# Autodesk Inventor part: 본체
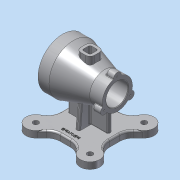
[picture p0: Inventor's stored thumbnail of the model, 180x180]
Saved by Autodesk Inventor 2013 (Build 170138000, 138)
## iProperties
Created: 2018-03
Part Number: 본체
Material: 알루미늄 6061
Document SubType Name: Modeling
Designer: dgall
Density: 2.71 g/cm^3
Mass: 1013.63 g
Surface Area: 870.735 cm^2
Volume: 374.034 cm^3
Author: dgall
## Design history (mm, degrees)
sketch "스케치1"
  geometry: L1 (0, 0)-(-68.205, 68.205); L2 (0, 0)-(-76.473, 0); L3 (-35.239, 60.483)-(-27.078, 52.322); L4 (-60.483, 35.239)-(-52.322, 27.078); L5 (-35.239, -60.483)-(-27.078, -52.322); L6 (-60.483, -35.239)-(-52.322, -27.078); L7 (0, 0)-(0, -76.473); L8 (0, 0)-(-68.205, -68.205); L9 (60.483, -35.239)-(52.322, -27.078); L10 (35.239, -60.483)-(27.078, -52.322); L11 (0, 0)-(76.473, 0); L12 (0, 0)-(68.205, -68.205); L13 (35.239, 60.483)-(27.078, 52.322); L14 (60.483, 35.239)-(52.322, 27.078); L15 (0, 0)-(0, 76.473); L16 (0, 0)-(68.205, 68.205); L17 (-9.4, 45)-(9.4, 45); L18 (32.068, 45)-(45, 45); L19 (45, 45)-(45, 32.068); L20 (45, 9.4)-(45, -9.4); L21 (45, -32.068)-(45, -45); L22 (45, -45)-(32.068, -45); L23 (9.4, -45)-(-9.4, -45); L24 (-32.068, -45)-(-45, -45); L25 (-45, -45)-(-45, -32.068); L26 (-45, -9.4)-(-45, 9.4); C1 r 5 at (-49.497, 49.497); C2 r 5 at (-49.497, -49.497); C3 r 5 at (49.497, -49.497); C4 r 5 at (49.497, 49.497); A1 r 18 centre (-49.497, 49.497) between (-35.239, 60.483) and (-60.483, 35.239); A2 r 25 centre (-9.4, 70) between (-27.078, 52.322) and (-9.4, 45); A3 r 25 centre (-70, 9.4) between (-45, 9.4) and (-52.322, 27.078); A4 r 18 centre (-49.497, -49.497) between (-60.483, -35.239) and (-35.239, -60.483); A5 r 25 centre (-70, -9.4) between (-52.322, -27.078) and (-45, -9.4); A6 r 25 centre (-9.4, -70) between (-9.4, -45) and (-27.078, -52.322); A7 r 18 centre (49.497, -49.497) between (35.239, -60.483) and (60.483, -35.239); A8 r 25 centre (9.4, -70) between (27.078, -52.322) and (9.4, -45); A9 r 25 centre (70, -9.4) between (45, -9.4) and (52.322, -27.078); A10 r 18 centre (49.497, 49.497) between (60.483, 35.239) and (35.239, 60.483); A11 r 25 centre (70, 9.4) between (52.322, 27.078) and (45, 9.4); A12 r 25 centre (9.4, 70) between (9.4, 45) and (27.078, 52.322); 5 further points
  constraints: 52 end point, 30 point on circle, 16 centre point, 13 parallel, 6 perpendicular, 6 tangent, 5 coincident, 4 horizontal, 4 point on line, 1 equal radius, 89 other
  dimensions: "d1" = 45 deg angle of L2 L1; "d2" = 10 diameter of C1; "d3" = 36 diameter of A1; "d4" = 90 distance of point (-45, 45) L18.end; "d5" = 90 distance of L18.end L21.end; "d6" = 25 radius of A2; "d9" = 360 deg dimension on point (0, 0) point (-45, 45) (derived)
extrude "돌출1" new body sketch "스케치1" distance "d11" = 12; taper "d12" = 0 deg
sketch "스케치2"
  geometry: L1 (-50, 82)-(50, 82); L2 (9.4, 0)-(27.078, 0) reference; L3 (0, 0)-(0, 110.069); L4 (-50, 127)-(-30, 127); L5 (-30, 127)-(27, 109.5); L6 (27, 109.5)-(50, 109.5); L7 (50, 109.5)-(50, 82); L8 (-50, 127)-(-50, 82)
  constraints: 14 end point, 2 parallel, 2 perpendicular, 1 horizontal
  dimensions: "d13" = 82 distance between parallel lines of L1 L2; "d14" = 50 distance from line of L4.start L3; "d15" = 20 distance of L4.start L4.end; "d16" = 77 horizontal distance of L5.end L4.start; "d17" = 100 horizontal distance of L4.start L6.end; "d19" = 90 diameter of L4 L1; "d21" = 55 diameter of L6 L1
revolve "회전1" sketch "스케치2" stored, may be unused: angle "d22" = 90 deg
sketch "스케치3"
  geometry: L1 (50, 54.5)-(50, 109.5) reference; L2 (50, 82)-(-50, 82); L3 (-50, 37)-(-50, 127) reference; L4 (-50, 82)-(-27, 82); L5 (-27, 82)-(-27, 117); L6 (-27, 117)-(-50, 117); L7 (-50, 117)-(-50, 82); L8 (-27, 82)-(20, 82); L9 (20, 82)-(20, 108); L10 (20, 108)-(-27, 108); L11 (-27, 108)-(-27, 82); L12 (20, 82)-(50, 82); L13 (50, 82)-(50, 102); L14 (50, 102)-(20, 102); L15 (20, 102)-(20, 82); 1 further point
  constraints: 26 end point, 6 parallel, 3 horizontal, 3 perpendicular, 2 midpoint, 1 point on line
  dimensions: "d23" = 23 distance of L5.end L6.end; "d25" = 47 distance of L9.end L10.end; "d26" = 30 distance of L13.end L14.end (derived); "d27" = 70 diameter of L6 L2; "d28" = 52 diameter of L10 L8; "d29" = 40 diameter of L14 L2
revolve "회전2" sketch "스케치3" stored, may be unused: angle "d30" = 90 deg
sketch "스케치4"
  geometry: L1 (0, 0)-(52.632, 0); C1 r 27.5 at (0, 0) reference; A1 r 27.5 centre (0, 0) between (27.5, 0) and (26.609, -6.943); A2 r 7 centre (27.5, 0) between (26.609, -6.943) and (26.609, 6.943); 1 further point
  constraints: 5 point on circle, 2 centre point, 2 end point, 1 coincident, 1 horizontal, 1 point on line
  dimensions: "d31" = 55 diameter of A1; "d32" = 14 diameter of A2
extrude "돌출2" join sketch "스케치4" distance "d33" = 15; taper "d34" = 0 deg
sketch "스케치5"
  geometry: A1 r 7 centre (0, 0) between (-0.891, -6.943) and (-0.891, 6.943) reference; 1 further point
hole "구멍1" sketch "스케치5" at (0, 0) diameter "d38" = 2.459; stored, may be unused: countersink angle "d42" = 90 deg, drill point angle "d44" = 118 deg; dims "d39" = 9, "d40" = 4, "d41" = 2, "d43" = 11
fillet "모깎기1" dims "d48" = 3
fillet "모깎기2" dims "d49" = 1
fillet "모깎기3" dims "d50" = 3
fillet "모깎기4" dims "d51" = 1
fillet "모깎기5" dims "d52" = 3
fillet "모깎기6" dims "d53" = 1
sketch "스케치6"
  geometry: L1 (9.4, 12)-(27.078, 12) reference; L2 (9.4, 12)-(-9.4, 12) reference; L3 (0, 12)-(-24, 12); L4 (-27.078, 12)-(-9.4, 12) reference; L5 (0, 82)-(0, 54.5); L6 (0, 54.5)-(0, 12); L7 (-24, 12)-(-19.566, 62.676); C1 r 20 at (0, 82) reference; C2 r 26 at (0, 82) reference; C3 r 26 at (0, 82) reference; A1 r 27.5 centre (0, 82) between (-19.566, 62.676) and (0, 54.5) reference; A2 r 45 centre (0, 82) between (0, 37) and (-21.342, 42.383) reference; 2 further points
  constraints: 8 end point, 4 point on circle, 3 point on line, 2 perpendicular, 1 coincident, 1 midpoint
  dimensions: "d54" = 24 distance of L3.start L3.end
extrude "돌출3" join sketch "스케치6" stored distance "d58" = 8; taper "d59" = 0 deg
sketch "스케치7"
  geometry: L1 (0, 0)-(0, 140.05); L2 (0, 0)-(-37, 0); L3 (-27.078, 0)-(-9.4, 0) reference; L4 (35.239, 0)-(27.078, 0) reference; L5 (-50, 37)-(-30, 37) reference; L6 (-30, 37)-(27, 54.5) reference; L7 (-37, 0)-(-37, 37); L8 (-37, 37)-(-30, 37); L9 (-4, 44.982)-(-4, 12); L10 (-4, 51.223)-(-4, 12) reference; L11 (-4, 12)-(-37, 12); L12 (0, 12.216)-(37, 12.216); L13 (9.4, 0)-(27.078, 0) reference; L14 (27, 54.5)-(50, 54.5) reference; L15 (27, 54.5)-(50, 54.5) reference; L16 (37, 12.216)-(37, 54.5); L17 (27, 54.5)-(-4, 44.982)
  constraints: 18 end point, 5 point on line, 4 collinear, 3 perpendicular, 1 parallel, 1 vertical
  dimensions: "d60" = 37 distance of L1.start L2.end; "d63" = 37 distance of L12.start L12.end
extrude "돌출4" join sketch "스케치7" stored distance "d61" = 8; taper "d62" = 0 deg
sketch "스케치8" dims "d64" = 80
  geometry: L1 (0, 0)-(-50.939, 0); C1 r 45 at (0, 0) reference; 2 further points
  constraints: 2 end point, 1 coincident, 1 horizontal, 1 horizontal alignment, 1 point on line, 2 other
hole "구멍2" sketch "스케치8" at (-40, 0) diameter "d65" = 3.242; stored, may be unused: countersink angle "d69" = 90 deg, drill point angle "d71" = 118 deg; dims "d66" = 9, "d67" = 4, "d68" = 2, "d70" = 11
chamfer "모따기1" distance "d75" = 1; stored, may be unused: second distance "d76" = 2, angle "d77" = 45 deg
chamfer "모따기2" distance "d78" = 1; stored, may be unused: second distance "d79" = 2, angle "d80" = 45 deg
fillet "모깎기7" dims "d81" = 3
fillet "모깎기8" dims "d82" = 3
fillet "모깎기9" dims "d83" = 3
fillet "모깎기10" dims "d84" = 3
fillet "모깎기11" dims "d85" = 3
fillet "모깎기12" dims "d86" = 3
fillet "모깎기13" dims "d87" = 3
fillet "모깎기14" dims "d88" = 3
fillet "모깎기15" dims "d89" = 3
fillet "모깎기16" dims "d90" = 3
fillet "모깎기17" dims "d91" = 3
fillet "모깎기18" dims "d92" = 3
fillet "모깎기19" dims "d93" = 3
sketch "스케치9"
  geometry: L1 (-45, 9.4)-(-45, -9.4) reference; 2 further points
  constraints: 1 other
  dimensions: "d94" = 45 distance from line of L1 point (0, 35); "d95" = 35 distance of point (0, 35) point (0, 0)
feature "엠보싱1" sketch "스케치9" dims "d9" = 360 deg (derived), "d96" = 0.5, "d97" = 0
node "작업 평면1"
sketch "스케치10"
  geometry: L1 (12.5, -12.5)-(-12.5, -12.5); L2 (-12.5, -12.5)-(-12.5, 12.5); L3 (-12.5, 12.5)-(12.5, 12.5); L4 (12.5, 12.5)-(12.5, -12.5); L5 (12.5, -12.5)-(-12.5, 12.5); L6 (-12.5, -12.5)-(12.5, 12.5); L7 (7.5, -7.5)-(-7.5, -7.5); L8 (-7.5, -7.5)-(-7.5, 7.5); L9 (-7.5, 7.5)-(7.5, 7.5); L10 (7.5, 7.5)-(7.5, -7.5); L11 (7.5, -7.5)-(-7.5, 7.5); L12 (-7.5, -7.5)-(7.5, 7.5); 1 further point
  constraints: 24 end point, 4 midpoint, 4 parallel, 2 horizontal, 2 perpendicular, 1 point on line
  dimensions: "d99" = 25 distance of L2.end L3.end; "d101" = 15 distance of L8.end L9.end; "d102" = 25 distance of L1.end L2.end; "d103" = 15 distance of L7.end L8.end (derived)
extrude "돌출5" join sketch "스케치10" stored distance "d104" = 10; taper "d105" = 0 deg
extrude "돌출6" cut sketch "스케치10" stored distance "d109" = 10; taper "d110" = 0 deg
fillet "모깎기23" dims "d111" = 8
fillet "모깎기24" dims "d112" = 3
node "솔리드1"
pattern_circular "원형 패턴1" dims angle "d36" = 360 deg
pattern_circular "원형 패턴2" dims angle "d46" = 360 deg
mirror "대칭1"
pattern_circular "원형 패턴3" dims angle "d73" = 360 deg
node "투영된 루프1"
node "투영된 루프2"
other parameters: "d56" = 95 deg, "d98" = 127
